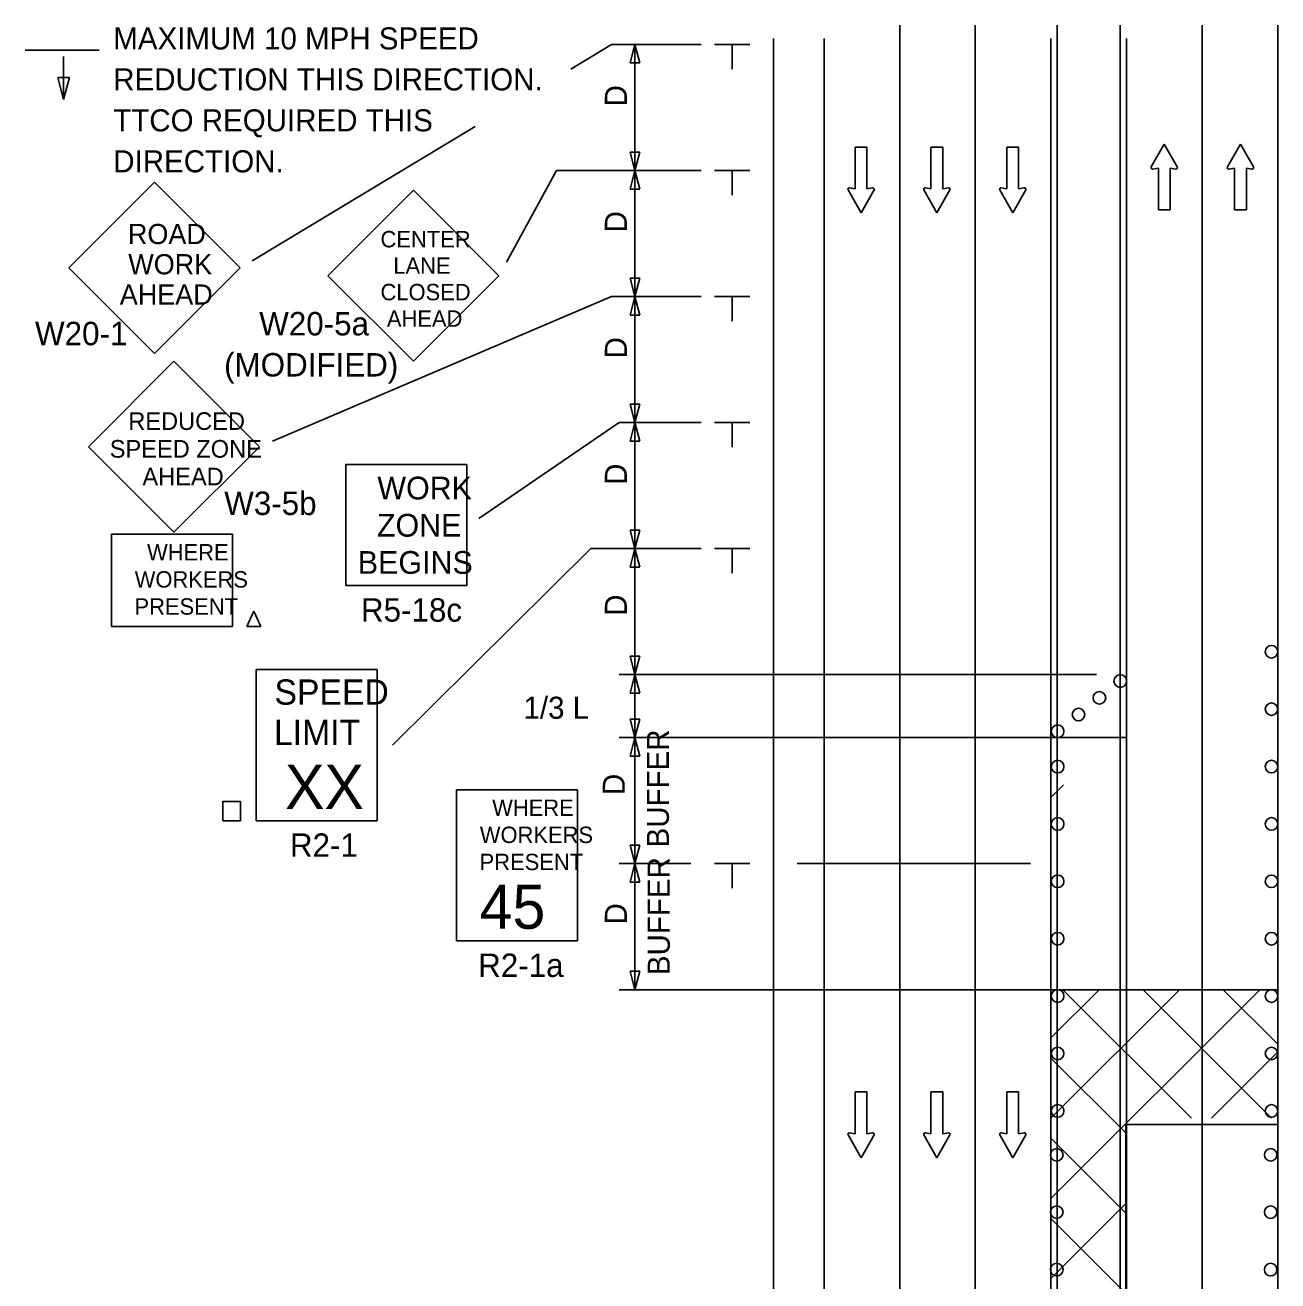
# Model space of a CAD drawing. Extents: x 16724 to 18475, y 5726 to 6929.
# Drawn here: x 16723.9 to 17121.4, y 6530.4 to 6929 of the extents above; entities that cross this region are included whole.
import ezdxf

# ---------------------------------------------------------------- set-up
doc = ezdxf.new("R2010")
doc.units = 0
for name, color, linetype in [('ALI_LEGAL_EX', 7, 'Continuous'), ('MT_SCRATCH_LEVEL_A', 7, 'Continuous'), ('MT_SCRATCH_LEVEL_E', 7, 'Continuous'), ('PAVT_EDGE_EX', 7, 'Continuous'), ('TRAFFIC_SIGNS_PR', 7, 'Continuous'), ('TYPICAL_TEXT_DIMEN_PR', 7, 'Continuous')]:
    doc.layers.add(name, color=color, linetype=linetype)

msp = doc.modelspace()

# ---------------------------------------------------------------- linework, layer by layer
at = {"layer": 'ALI_LEGAL_EX'}
for p, q in [((17001.36, 6131.68), (17001.36, 6928.96)), ((17025.36, 6131.68), (17025.36, 6928.96)), ((17051.36, 6131.68), (17051.36, 6928.96)), ((17071.36, 6131.68), (17071.36, 6928.96)), ((17097.36, 6131.68), (17097.36, 6928.96)), ((17121.36, 6131.68), (17121.36, 6928.96))]:
    msp.add_line(p, q, dxfattribs=at)
for points in [[(17001.36, 6831.68), (17001.36, 6856.68)], [(17025.36, 6831.68), (17025.36, 6856.68)], [(17051.36, 6831.68), (17051.36, 6856.68)], [(17071.36, 6831.68), (17071.36, 6856.68)], [(17097.36, 6831.68), (17097.36, 6856.68)], [(17121.36, 6831.68), (17121.36, 6856.68)], [(17001.36, 6731.68), (17001.36, 6756.68)], [(17025.36, 6731.68), (17025.36, 6756.68)], [(17051.36, 6731.68), (17051.36, 6756.68)], [(17071.36, 6731.68), (17071.36, 6756.68)], [(17097.36, 6731.68), (17097.36, 6756.68)], [(17121.36, 6731.68), (17121.36, 6756.68)], [(17001.36, 6631.68), (17001.36, 6656.68)], [(17025.36, 6631.68), (17025.36, 6656.68)], [(17051.36, 6631.68), (17051.36, 6656.68)], [(17071.36, 6631.68), (17071.36, 6656.68)], [(17097.36, 6631.68), (17097.36, 6656.68)], [(17121.36, 6631.68), (17121.36, 6656.68)], [(17001.36, 6531.68), (17001.36, 6556.68)], [(17025.36, 6531.68), (17025.36, 6556.68)], [(17051.36, 6531.68), (17051.36, 6556.68)], [(17071.36, 6531.68), (17071.36, 6556.68)], [(17097.36, 6531.68), (17097.36, 6556.68)]]:
    msp.add_lwpolyline(points, dxfattribs=at)
at = {"layer": 'MT_SCRATCH_LEVEL_A'}
for p, q in [((17049.36, 6727.81), (17049.36, 6549.97)), ((17049.36, 6695.75), (17049.36, 6582.03)), ((17049.36, 6683.85), (17053.32, 6687.81)), ((17049.36, 6607.48), (17064.68, 6622.81)), ((17049.36, 6582.03), (17090.14, 6622.81)), ((17049.36, 6556.57), (17115.6, 6622.81)), ((17049.36, 6622.81), (17121.36, 6622.81)), ((17093.9, 6582.03), (17053.12, 6622.81)), ((17119.36, 6582.03), (17078.58, 6622.81)), ((17121.36, 6605.48), (17104.03, 6622.81)), ((17073.11, 6577.36), (17049.36, 6601.12)), ((17100.27, 6582.03), (17121.36, 6603.11)), ((17073.36, 6551.66), (17049.36, 6575.66)), ((17049.36, 6531.11), (17073.36, 6555.11)), ((17073.36, 6526.21), (17049.36, 6550.21))]:
    msp.add_line(p, q, dxfattribs=at)
at = {"layer": 'MT_SCRATCH_LEVEL_E'}
for p, q in [((16990.96, 6890.26), (16987.21, 6890.26)), ((16987.21, 6890.26), (16987.21, 6877.01)), ((16990.96, 6890.26), (16987.21, 6890.26)), ((16987.21, 6890.26), (16987.21, 6877.01)), ((16990.96, 6877.01), (16990.96, 6890.26)), ((16990.96, 6877.01), (16990.96, 6890.26)), ((17015.03, 6890.26), (17011.28, 6890.26)), ((17011.28, 6890.26), (17011.28, 6877.01)), ((17015.03, 6890.26), (17011.28, 6890.26)), ((17011.28, 6890.26), (17011.28, 6877.01)), ((17015.03, 6877.01), (17015.03, 6890.26)), ((17015.03, 6877.01), (17015.03, 6890.26)), ((17039.1, 6890.26), (17035.35, 6890.26)), ((17035.35, 6890.26), (17035.35, 6877.01)), ((17039.1, 6890.26), (17035.35, 6890.26)), ((17035.35, 6890.26), (17035.35, 6877.01)), ((17039.1, 6877.01), (17039.1, 6890.26)), ((17039.1, 6877.01), (17039.1, 6890.26)), ((17085.29, 6891.21), (17081.18, 6883.97)), ((17085.29, 6891.21), (17081.18, 6883.97)), ((17089.44, 6883.97), (17085.29, 6891.21)), ((17089.44, 6883.97), (17085.29, 6891.21)), ((17109.46, 6891.21), (17105.35, 6883.97)), ((17109.46, 6891.21), (17105.35, 6883.97)), ((17113.61, 6883.97), (17109.46, 6891.21)), ((17113.61, 6883.97), (17109.46, 6891.21)), ((17081.66, 6883.28), (17083.44, 6883.6)), ((17081.66, 6883.28), (17083.44, 6883.6)), ((17083.44, 6883.6), (17083.44, 6870.34)), ((17083.44, 6883.6), (17083.44, 6870.34)), ((17087.18, 6870.34), (17087.18, 6883.6)), ((17087.18, 6883.6), (17088.96, 6883.28)), ((17087.18, 6870.34), (17087.18, 6883.6)), ((17087.18, 6883.6), (17088.96, 6883.28)), ((17105.83, 6883.28), (17107.61, 6883.6)), ((17105.83, 6883.28), (17107.61, 6883.6)), ((17107.61, 6883.6), (17107.61, 6870.34)), ((17107.61, 6883.6), (17107.61, 6870.34)), ((17111.35, 6870.34), (17111.35, 6883.6)), ((17111.35, 6883.6), (17113.13, 6883.28)), ((17111.35, 6870.34), (17111.35, 6883.6)), ((17111.35, 6883.6), (17113.13, 6883.28)), ((16984.96, 6876.64), (16989.1, 6869.4)), ((16984.96, 6876.64), (16989.1, 6869.4)), ((16987.21, 6877.01), (16985.44, 6877.32)), ((16987.21, 6877.01), (16985.44, 6877.32)), ((16989.1, 6869.4), (16993.21, 6876.64)), ((16989.1, 6869.4), (16993.21, 6876.64)), ((16992.73, 6877.32), (16990.96, 6877.01)), ((16992.73, 6877.32), (16990.96, 6877.01)), ((17009.03, 6876.64), (17013.17, 6869.4)), ((17009.03, 6876.64), (17013.17, 6869.4)), ((17011.28, 6877.01), (17009.51, 6877.32)), ((17011.28, 6877.01), (17009.51, 6877.32)), ((17013.17, 6869.4), (17017.28, 6876.64)), ((17013.17, 6869.4), (17017.28, 6876.64)), ((17016.8, 6877.32), (17015.03, 6877.01)), ((17016.8, 6877.32), (17015.03, 6877.01)), ((17033.1, 6876.64), (17037.24, 6869.4)), ((17033.1, 6876.64), (17037.24, 6869.4)), ((17035.35, 6877.01), (17033.58, 6877.32)), ((17035.35, 6877.01), (17033.58, 6877.32)), ((17037.24, 6869.4), (17041.36, 6876.64)), ((17037.24, 6869.4), (17041.36, 6876.64)), ((17040.87, 6877.32), (17039.1, 6877.01)), ((17040.87, 6877.32), (17039.1, 6877.01)), ((17083.44, 6870.34), (17087.18, 6870.34)), ((17083.44, 6870.34), (17087.18, 6870.34)), ((17107.61, 6870.34), (17111.35, 6870.34)), ((17107.61, 6870.34), (17111.35, 6870.34)), ((16990.96, 6590.35), (16987.21, 6590.35)), ((16987.21, 6590.35), (16987.21, 6577.09)), ((16990.96, 6590.35), (16987.21, 6590.35)), ((16987.21, 6590.35), (16987.21, 6577.09)), ((16990.96, 6577.09), (16990.96, 6590.35)), ((16990.96, 6577.09), (16990.96, 6590.35)), ((17015.03, 6590.35), (17011.28, 6590.35)), ((17011.28, 6590.35), (17011.28, 6577.09)), ((17015.03, 6590.35), (17011.28, 6590.35)), ((17011.28, 6590.35), (17011.28, 6577.09)), ((17015.03, 6577.09), (17015.03, 6590.35)), ((17015.03, 6577.09), (17015.03, 6590.35)), ((17039.1, 6590.35), (17035.35, 6590.35)), ((17035.35, 6590.35), (17035.35, 6577.09)), ((17039.1, 6590.35), (17035.35, 6590.35)), ((17035.35, 6590.35), (17035.35, 6577.09)), ((17039.1, 6577.09), (17039.1, 6590.35)), ((17039.1, 6577.09), (17039.1, 6590.35)), ((16984.96, 6576.72), (16989.1, 6569.48)), ((16984.96, 6576.72), (16989.1, 6569.48)), ((16987.21, 6577.09), (16985.44, 6577.4)), ((16987.21, 6577.09), (16985.44, 6577.4)), ((16989.1, 6569.48), (16993.21, 6576.72)), ((16989.1, 6569.48), (16993.21, 6576.72)), ((16992.73, 6577.4), (16990.96, 6577.09)), ((16992.73, 6577.4), (16990.96, 6577.09)), ((17009.03, 6576.72), (17013.17, 6569.48)), ((17009.03, 6576.72), (17013.17, 6569.48)), ((17011.28, 6577.09), (17009.51, 6577.4)), ((17011.28, 6577.09), (17009.51, 6577.4)), ((17013.17, 6569.48), (17017.28, 6576.72)), ((17013.17, 6569.48), (17017.28, 6576.72)), ((17016.8, 6577.4), (17015.03, 6577.09)), ((17016.8, 6577.4), (17015.03, 6577.09)), ((17033.1, 6576.72), (17037.24, 6569.48)), ((17033.1, 6576.72), (17037.24, 6569.48)), ((17035.35, 6577.09), (17033.58, 6577.4)), ((17035.35, 6577.09), (17033.58, 6577.4)), ((17037.24, 6569.48), (17041.36, 6576.72)), ((17037.24, 6569.48), (17041.36, 6576.72)), ((17040.87, 6577.4), (17039.1, 6577.09)), ((17040.87, 6577.4), (17039.1, 6577.09))]:
    msp.add_line(p, q, dxfattribs=at)
for centre, start, end in [((17081.59, 6883.74), 150.4248, 279.9638), ((17081.59, 6883.74), 150.4248, 279.9638), ((17089.03, 6883.74), 260.0362, 29.7731), ((17089.03, 6883.74), 260.0362, 29.7731), ((17105.76, 6883.74), 150.4248, 279.9638), ((17105.76, 6883.74), 150.4248, 279.9638), ((17113.2, 6883.74), 260.0362, 29.7731), ((17113.2, 6883.74), 260.0362, 29.7731), ((16985.37, 6876.86), 80.0362, 209.7731), ((16985.37, 6876.86), 80.0362, 209.7731), ((16992.81, 6876.86), 330.4248, 99.9638), ((16992.81, 6876.86), 330.4248, 99.9638), ((17009.44, 6876.86), 80.0362, 209.7731), ((17009.44, 6876.86), 80.0362, 209.7731), ((17016.88, 6876.86), 330.4248, 99.9638), ((17016.88, 6876.86), 330.4248, 99.9638), ((17033.51, 6876.86), 80.0362, 209.7731), ((17033.51, 6876.86), 80.0362, 209.7731), ((17040.95, 6876.86), 330.4248, 99.9638), ((17040.95, 6876.86), 330.4248, 99.9638), ((16985.37, 6576.94), 80.0362, 209.7731), ((16985.37, 6576.94), 80.0362, 209.7731), ((16992.81, 6576.94), 330.4248, 99.9638), ((16992.81, 6576.94), 330.4248, 99.9638), ((17009.44, 6576.94), 80.0362, 209.7731), ((17009.44, 6576.94), 80.0362, 209.7731), ((17016.88, 6576.94), 330.4248, 99.9638), ((17016.88, 6576.94), 330.4248, 99.9638), ((17033.51, 6576.94), 80.0362, 209.7731), ((17033.51, 6576.94), 80.0362, 209.7731), ((17040.95, 6576.94), 330.4248, 99.9638), ((17040.95, 6576.94), 330.4248, 99.9638)]:
    msp.add_arc(centre, 0.463, start, end, dxfattribs=at)
at = {"layer": 'PAVT_EDGE_EX'}
for p, q in [((16961.36, 6924.76), (16961.36, 6059.7)), ((16977.36, 6924.76), (16977.36, 6059.7)), ((17049.36, 6924.76), (17049.36, 6059.7)), ((17073.36, 6924.76), (17073.36, 6059.7))]:
    msp.add_line(p, q, dxfattribs=at)
for points in [[(17073.36, 6702.81), (17049.36, 6702.81), (17049.36, 6622.81), (17073.36, 6622.81)], [(17121.36, 6579.99), (17073.11, 6579.99), (17073.11, 6499.97), (17121.36, 6499.97)]]:
    msp.add_lwpolyline(points, close=True, dxfattribs=at)
at = {"layer": 'TRAFFIC_SIGNS_PR'}
for p, q in [((16764.94, 6879.08), (16737.78, 6851.92)), ((16792.09, 6851.92), (16764.94, 6879.08)), ((16847.05, 6876.56), (16819.9, 6849.41)), ((16874.2, 6849.41), (16847.05, 6876.56)), ((16737.78, 6851.92), (16764.94, 6824.77)), ((16764.94, 6824.77), (16792.09, 6851.92)), ((16819.9, 6849.41), (16847.05, 6822.26)), ((16847.05, 6822.26), (16874.2, 6849.41)), ((16771.07, 6822.31), (16743.92, 6795.16)), ((16798.22, 6795.16), (16771.07, 6822.31)), ((16743.92, 6795.16), (16771.07, 6768.01)), ((16771.07, 6768.01), (16798.22, 6795.16)), ((16825.62, 6751.06), (16825.62, 6789.46)), ((16825.62, 6789.46), (16864.02, 6789.46)), ((16864.02, 6751.06), (16864.02, 6789.46)), ((16751.25, 6767.36), (16789.65, 6767.36)), ((16751.25, 6738.04), (16751.25, 6767.36)), ((16789.65, 6738.04), (16789.65, 6767.36)), ((16825.62, 6751.06), (16864.02, 6751.06)), ((16751.25, 6738.04), (16789.65, 6738.04)), ((16797.21, 6724.42), (16835.61, 6724.42)), ((16797.21, 6676.42), (16797.21, 6724.42)), ((16835.61, 6676.42), (16835.61, 6724.42)), ((16860.75, 6686.28), (16899.15, 6686.28)), ((16860.75, 6638.28), (16860.75, 6686.28)), ((16899.15, 6638.28), (16899.15, 6686.28)), ((16797.21, 6676.42), (16835.61, 6676.42)), ((16860.75, 6638.28), (16899.15, 6638.28))]:
    msp.add_line(p, q, dxfattribs=at)
for points in [[(16796.4, 6742.98), (16794.16, 6738.04)], [(16794.16, 6738.04), (16796.4, 6742.98)], [(16798.64, 6738.04), (16796.4, 6742.98)], [(16796.4, 6742.98), (16798.64, 6738.04)], [(16794.16, 6738.04), (16798.64, 6738.04)], [(16798.64, 6738.04), (16794.16, 6738.04)]]:
    msp.add_lwpolyline(points, dxfattribs=at)
msp.add_lwpolyline([(16786.6, 6676.42), (16792.19, 6676.42), (16792.19, 6682.59), (16786.6, 6682.59)], close=True, dxfattribs=at)
for centre in [(17119.33, 6730.06), (17071.35, 6720.77), (17064.72, 6715.45), (17058.09, 6710.14), (17119.33, 6711.84), (17051.45, 6704.82), (17051.46, 6693.63), (17119.33, 6693.63), (17051.46, 6675.41), (17119.33, 6675.41), (17051.46, 6657.2), (17119.33, 6657.2), (17051.46, 6638.99), (17119.33, 6638.99), (17051.46, 6620.77), (17119.33, 6620.77), (17051.46, 6602.56), (17119.33, 6602.56), (17051.46, 6584.34), (17119.33, 6584.34), (17051.2, 6570.4), (17119.07, 6570.4), (17051.2, 6552.19), (17119.07, 6552.19), (17051.2, 6533.97), (17119.07, 6533.97)]:
    msp.add_circle(centre, 2, dxfattribs=at)
at = {"layer": 'TYPICAL_TEXT_DIMEN_PR'}
for p, q in [((16747.41, 6921.01), (16723.86, 6921.01)), ((16897, 6915.02), (16909.94, 6922.8)), ((16909.94, 6922.8), (16938.36, 6922.8)), ((16915.79, 6916.94), (16917.36, 6922.8)), ((16917.36, 6922.8), (16917.36, 6882.8)), ((16917.36, 6922.8), (16918.93, 6916.94)), ((16942.61, 6922.8), (16953.86, 6922.8)), ((16948.23, 6922.8), (16948.23, 6915.02)), ((16736.08, 6919.01), (16736.08, 6905.31)), ((16917.36, 6916.94), (16915.79, 6916.94)), ((16918.93, 6916.94), (16917.36, 6916.94)), ((16736.08, 6912.35), (16734.19, 6912.35)), ((16734.19, 6912.35), (16736.08, 6905.31)), ((16736.08, 6905.31), (16737.96, 6912.35)), ((16737.96, 6912.35), (16736.08, 6912.35)), ((16795.86, 6854.19), (16866.7, 6896.8)), ((16917.36, 6882.8), (16915.79, 6888.66)), ((16915.79, 6888.66), (16917.36, 6888.66)), ((16917.36, 6888.66), (16918.93, 6888.66)), ((16918.93, 6888.66), (16917.36, 6882.8)), ((16876.59, 6853.77), (16892.47, 6882.8)), ((16917.36, 6882.8), (16892.47, 6882.8)), ((16915.79, 6876.94), (16917.36, 6882.8)), ((16917.36, 6882.8), (16917.36, 6842.8)), ((16917.36, 6882.8), (16918.93, 6876.94)), ((16917.36, 6882.8), (16938.36, 6882.8)), ((16942.61, 6882.8), (16953.86, 6882.8)), ((16948.23, 6882.8), (16948.23, 6875.02)), ((16917.36, 6876.94), (16915.79, 6876.94)), ((16918.93, 6876.94), (16917.36, 6876.94)), ((16917.36, 6842.8), (16915.79, 6848.66)), ((16915.79, 6848.66), (16917.36, 6848.66)), ((16917.36, 6848.66), (16918.93, 6848.66)), ((16918.93, 6848.66), (16917.36, 6842.8)), ((16909.94, 6842.8), (16802.37, 6796.93)), ((16909.94, 6842.8), (16938.36, 6842.8)), ((16915.79, 6836.94), (16917.36, 6842.8)), ((16917.36, 6842.8), (16917.36, 6802.8)), ((16917.36, 6842.8), (16918.93, 6836.94)), ((16942.61, 6842.8), (16953.86, 6842.8)), ((16948.23, 6842.8), (16948.23, 6835.02)), ((16917.36, 6836.94), (16915.79, 6836.94)), ((16918.93, 6836.94), (16917.36, 6836.94)), ((16917.36, 6802.8), (16915.79, 6808.66)), ((16915.79, 6808.66), (16917.36, 6808.66)), ((16917.36, 6808.66), (16918.93, 6808.66)), ((16918.93, 6808.66), (16917.36, 6802.8)), ((16912.36, 6802.8), (16867.8, 6772.36)), ((16912.36, 6802.8), (16938.36, 6802.8)), ((16915.79, 6796.94), (16917.36, 6802.8)), ((16917.36, 6802.8), (16917.36, 6762.8)), ((16917.36, 6802.8), (16918.93, 6796.94)), ((16942.61, 6802.8), (16953.86, 6802.8)), ((16948.23, 6802.8), (16948.23, 6795.02)), ((16917.36, 6796.94), (16915.79, 6796.94)), ((16918.93, 6796.94), (16917.36, 6796.94)), ((16917.36, 6762.8), (16915.79, 6768.66)), ((16915.79, 6768.66), (16917.36, 6768.66)), ((16917.36, 6768.66), (16918.93, 6768.66)), ((16918.93, 6768.66), (16917.36, 6762.8)), ((16840.46, 6700.47), (16903.41, 6762.8)), ((16903.41, 6762.8), (16938.36, 6762.8)), ((16915.79, 6756.94), (16917.36, 6762.8)), ((16917.36, 6762.8), (16918.93, 6756.94)), ((16917.36, 6762.8), (16917.36, 6722.8)), ((16942.61, 6762.8), (16953.86, 6762.8)), ((16948.23, 6762.8), (16948.23, 6755.02)), ((16917.36, 6756.94), (16915.79, 6756.94)), ((16918.93, 6756.94), (16917.36, 6756.94)), ((16917.36, 6722.8), (16915.79, 6728.66)), ((16915.79, 6728.66), (16917.36, 6728.66)), ((16917.36, 6728.66), (16918.93, 6728.66)), ((16918.93, 6728.66), (16917.36, 6722.8)), ((16912.36, 6722.8), (17063.81, 6722.8)), ((16915.79, 6716.94), (16917.36, 6722.8)), ((16917.36, 6722.8), (16917.36, 6702.81)), ((16917.36, 6722.8), (16918.93, 6716.94)), ((16917.36, 6716.94), (16915.79, 6716.94)), ((16918.93, 6716.94), (16917.36, 6716.94)), ((16917.36, 6702.81), (16915.79, 6708.67)), ((16915.79, 6708.67), (16917.36, 6708.67)), ((16917.36, 6708.67), (16918.93, 6708.67)), ((16918.93, 6708.67), (16917.36, 6702.81)), ((16912.36, 6702.81), (17073.36, 6702.81)), ((16915.79, 6696.95), (16917.36, 6702.81)), ((16917.36, 6702.81), (16918.93, 6696.95)), ((16917.36, 6702.81), (16917.36, 6662.81)), ((16917.36, 6696.95), (16915.79, 6696.95)), ((16918.93, 6696.95), (16917.36, 6696.95)), ((16917.36, 6662.81), (16915.79, 6668.67)), ((16915.79, 6668.67), (16917.36, 6668.67)), ((16917.36, 6668.67), (16918.93, 6668.67)), ((16918.93, 6668.67), (16917.36, 6662.81)), ((16912.36, 6662.81), (16935.07, 6662.81)), ((16915.79, 6656.95), (16917.36, 6662.81)), ((16917.36, 6662.81), (16918.93, 6656.95)), ((16917.36, 6662.81), (16917.36, 6622.81)), ((16942.61, 6662.81), (16953.86, 6662.81)), ((16948.23, 6662.81), (16948.23, 6655.02)), ((16968.87, 6662.81), (17042.86, 6662.81)), ((16917.36, 6656.95), (16915.79, 6656.95)), ((16918.93, 6656.95), (16917.36, 6656.95)), ((16917.36, 6622.81), (16915.79, 6628.67)), ((16915.79, 6628.67), (16917.36, 6628.67)), ((16917.36, 6628.67), (16918.93, 6628.67)), ((16918.93, 6628.67), (16917.36, 6622.81)), ((16912.36, 6622.81), (17049.36, 6622.81)), ((16912.36, 6622.81), (17049.36, 6622.81))]:
    msp.add_line(p, q, dxfattribs=at)

# ---------------------------------------------------------------- texts
at = {"layer": 'TRAFFIC_SIGNS_PR'}
for s, height, p in [('ROAD', 6.4, (16756.48, 6859.46)), ('CENTER', 5.2, (16836.63, 6858.42)), ('WORK', 6.4, (16756.59, 6849.86)), ('LANE', 5.2, (16840.7, 6850.02)), ('AHEAD', 6.4, (16753.9, 6840.26)), ('CLOSED', 5.2, (16836.63, 6841.62)), ('W20-5a', 7.44, (16798.14, 6830.47)), ('AHEAD', 5.2, (16838.65, 6833.22)), ('W20-1', 7.44, (16727.01, 6827.35)), ('(MODIFIED)', 7.44, (16787, 6817.43)), ('REDUCED', 5.6, (16756.6, 6800.47)), ('SPEED ZONE', 5.6, (16750.71, 6791.67)), ('AHEAD', 5.6, (16761.08, 6782.87)), ('WORK', 7.217, (16835.62, 6778.42)), ('W3-5b', 7.44, (16787.04, 6773.48)), ('ZONE', 7.217, (16835.5, 6766.61)), ('WHERE', 5.2, (16762.56, 6759.04)), ('BEGINS', 7.217, (16829.43, 6754.8)), ('WORKERS', 5.2, (16758.64, 6750.44)), ('PRESENT', 5.2, (16758.57, 6741.84)), ('R5-18c', 7.44, (16830.43, 6739.62)), ('SPEED', 8, (16802.98, 6713.28)), ('LIMIT', 8, (16802.82, 6700.48)), ('XX', 14.031, (16806.32, 6680.18)), ('WHERE', 5.2, (16872.06, 6677.96)), ('R2-1', 7.44, (16807.89, 6664.98)), ('WORKERS', 5.2, (16868.14, 6669.36)), ('PRESENT', 5.2, (16868.07, 6660.76)), ('45', 14.031, (16868.06, 6642.13)), ('R2-1a', 7.44, (16867.61, 6626.84))]:
    msp.add_text(s, height=height, dxfattribs=at).set_placement(p)
at = {"layer": 'TYPICAL_TEXT_DIMEN_PR'}
for s, p in [('MAXIMUM 10 MPH SPEED', (16751.83, 6921.23)), ('REDUCTION THIS DIRECTION.', (16751.83, 6908.23)), ('TTCO REQUIRED THIS', (16751.83, 6895.23)), ('DIRECTION.', (16751.83, 6882.23)), ('1/3 L', (16881.99, 6708.81))]:
    msp.add_text(s, height=7, dxfattribs=at).set_placement(p)
for s, p in [('D', (16914.8, 6903.17)), ('D', (16914.8, 6863.17)), ('D', (16914.8, 6823.17)), ('D', (16914.8, 6783.02)), ('D', (16914.8, 6741.47)), ('BUFFER', (16928.13, 6667.96)), ('D', (16914.14, 6684.6)), ('BUFFER', (16928.41, 6627.43)), ('D', (16914.8, 6643.49))]:
    msp.add_text(s, height=7, rotation=90, dxfattribs=at).set_placement(p)

doc.saveas('drawing.dxf')
